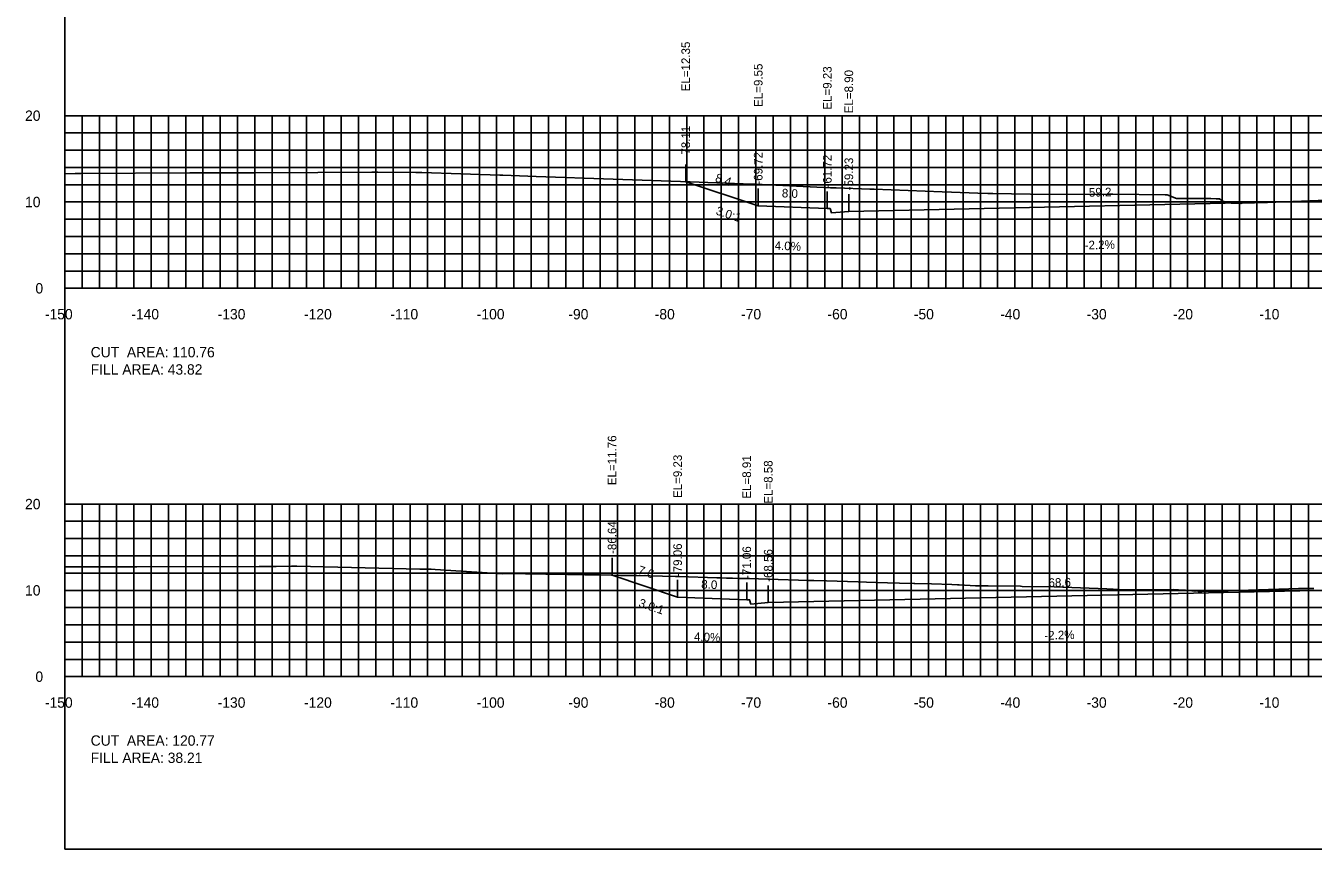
# Model space of a CAD drawing. Extents: x 1797419 to 1809236, y 248759 to 251512.
# Drawn here: x 1804176.5 to 1804325.5, y 250854.9 to 250950.3 of the extents above; entities that cross this region are included whole.
import ezdxf

# ---------------------------------------------------------------- set-up
doc = ezdxf.new("R2010")
doc.units = 0
for name, color, linetype in [('10', 7, 'Continuous'), ('3', 7, 'Continuous'), ('31', 7, 'Continuous'), ('4', 7, 'Continuous'), ('60', 7, 'Continuous'), ('ANNO-TXT', 7, 'Continuous'), ('CL-CNST', 7, 'Continuous'), ('Level 62', 7, 'Continuous'), ('M-ROADS', 7, 'Continuous')]:
    doc.layers.add(name, color=color, linetype=linetype)

msp = doc.modelspace()

# ---------------------------------------------------------------- linework, layer by layer
for p, q in [((1804252.89, 250932.24), (1804252.89, 250934.24)), ((1804261.28, 250929.44), (1804261.28, 250931.44)), ((1804269.28, 250929.12), (1804269.28, 250931.12)), ((1804271.77, 250928.79), (1804271.77, 250930.79)), ((1804244.36, 250886.65), (1804244.36, 250888.65)), ((1804251.95, 250884.12), (1804251.95, 250886.12)), ((1804259.95, 250883.8), (1804259.95, 250885.8)), ((1804262.44, 250883.47), (1804262.44, 250885.47))]:
    msp.add_line(p, q)
msp.add_lwpolyline([(1804181, 250854.89), (1804481, 250854.89), (1804481, 251044.89), (1804181, 251044.89)], close=True)
at = {"layer": '60'}
for p, q in [((1804180.94, 250939.89), (1804181, 250939.89)), ((1804181, 250919.89), (1804181, 250939.89)), ((1804180.94, 250929.89), (1804181, 250929.89)), ((1804180.94, 250919.89), (1804181, 250919.89)), ((1804181, 250919.89), (1804481, 250919.89)), ((1804181, 250919.83), (1804181, 250919.89)), ((1804191, 250919.83), (1804191, 250919.89)), ((1804201, 250919.83), (1804201, 250919.89)), ((1804211, 250919.83), (1804211, 250919.89)), ((1804221, 250919.83), (1804221, 250919.89)), ((1804231, 250919.83), (1804231, 250919.89)), ((1804241, 250919.83), (1804241, 250919.89)), ((1804251, 250919.83), (1804251, 250919.89)), ((1804261, 250919.83), (1804261, 250919.89)), ((1804271, 250919.83), (1804271, 250919.89)), ((1804281, 250919.83), (1804281, 250919.89)), ((1804291, 250919.83), (1804291, 250919.89)), ((1804301, 250919.83), (1804301, 250919.89)), ((1804311, 250919.83), (1804311, 250919.89)), ((1804321, 250919.83), (1804321, 250919.89)), ((1804180.94, 250894.89), (1804181, 250894.89)), ((1804181, 250874.89), (1804181, 250894.89)), ((1804180.94, 250884.89), (1804181, 250884.89)), ((1804180.94, 250874.89), (1804181, 250874.89)), ((1804181, 250874.89), (1804481, 250874.89)), ((1804181, 250874.83), (1804181, 250874.89)), ((1804191, 250874.83), (1804191, 250874.89)), ((1804201, 250874.83), (1804201, 250874.89)), ((1804211, 250874.83), (1804211, 250874.89)), ((1804221, 250874.83), (1804221, 250874.89)), ((1804231, 250874.83), (1804231, 250874.89)), ((1804241, 250874.83), (1804241, 250874.89)), ((1804251, 250874.83), (1804251, 250874.89)), ((1804261, 250874.83), (1804261, 250874.89)), ((1804271, 250874.83), (1804271, 250874.89)), ((1804281, 250874.83), (1804281, 250874.89)), ((1804291, 250874.83), (1804291, 250874.89)), ((1804301, 250874.83), (1804301, 250874.89)), ((1804311, 250874.83), (1804311, 250874.89)), ((1804321, 250874.83), (1804321, 250874.89))]:
    msp.add_line(p, q, dxfattribs=at)
at = {"layer": 'CL-CNST'}
for points in [[(1804252.89, 250932.24), (1804261.28, 250929.44), (1804269.28, 250929.12), (1804269.61, 250929.12), (1804269.77, 250928.62), (1804271.77, 250928.79), (1804331, 250930.09), (1804387.97, 250931.34), (1804389.97, 250931.18), (1804390.14, 250931.68), (1804390.47, 250931.68), (1804392.47, 250931.76), (1804393.5, 250931.78), (1804398.5, 250931.88), (1804399.5, 250931.92), (1804403.32, 250930.65)], [(1804244.36, 250886.65), (1804251.95, 250884.12), (1804259.95, 250883.8), (1804260.28, 250883.8), (1804260.44, 250883.3), (1804262.44, 250883.47), (1804331, 250884.98), (1804380.14, 250886.06), (1804382.14, 250885.89), (1804382.3, 250886.39), (1804382.63, 250886.39), (1804384.63, 250886.47), (1804393.06, 250886.45), (1804398.41, 250886.56), (1804399.41, 250886.6), (1804401.92, 250885.76)]]:
    msp.add_lwpolyline(points, dxfattribs=at)
at = {"layer": 'Level 62'}
for p, q in [((1804181, 250939.89), (1804481, 250939.89)), ((1804181, 250919.89), (1804181, 250939.89)), ((1804183, 250919.89), (1804183, 250939.89)), ((1804185, 250919.89), (1804185, 250939.89)), ((1804187, 250919.89), (1804187, 250939.89)), ((1804189, 250919.89), (1804189, 250939.89)), ((1804191, 250919.89), (1804191, 250939.89)), ((1804193, 250919.89), (1804193, 250939.89)), ((1804195, 250919.89), (1804195, 250939.89)), ((1804197, 250919.89), (1804197, 250939.89)), ((1804199, 250919.89), (1804199, 250939.89)), ((1804201, 250919.89), (1804201, 250939.89)), ((1804203, 250919.89), (1804203, 250939.89)), ((1804205, 250919.89), (1804205, 250939.89)), ((1804207, 250919.89), (1804207, 250939.89)), ((1804209, 250919.89), (1804209, 250939.89)), ((1804211, 250919.89), (1804211, 250939.89)), ((1804213, 250919.89), (1804213, 250939.89)), ((1804215, 250919.89), (1804215, 250939.89)), ((1804217, 250919.89), (1804217, 250939.89)), ((1804219, 250919.89), (1804219, 250939.89)), ((1804221, 250919.89), (1804221, 250939.89)), ((1804223, 250919.89), (1804223, 250939.89)), ((1804225, 250919.89), (1804225, 250939.89)), ((1804227, 250919.89), (1804227, 250939.89)), ((1804229, 250919.89), (1804229, 250939.89)), ((1804231, 250919.89), (1804231, 250939.89)), ((1804233, 250919.89), (1804233, 250939.89)), ((1804235, 250919.89), (1804235, 250939.89)), ((1804237, 250919.89), (1804237, 250939.89)), ((1804239, 250919.89), (1804239, 250939.89)), ((1804241, 250919.89), (1804241, 250939.89)), ((1804243, 250919.89), (1804243, 250939.89)), ((1804245, 250919.89), (1804245, 250939.89)), ((1804247, 250919.89), (1804247, 250939.89)), ((1804249, 250919.89), (1804249, 250939.89)), ((1804251, 250919.89), (1804251, 250939.89)), ((1804253, 250919.89), (1804253, 250939.89)), ((1804255, 250919.89), (1804255, 250939.89)), ((1804257, 250919.89), (1804257, 250939.89)), ((1804259, 250919.89), (1804259, 250939.89)), ((1804261, 250919.89), (1804261, 250939.89)), ((1804263, 250919.89), (1804263, 250939.89)), ((1804265, 250919.89), (1804265, 250939.89)), ((1804267, 250919.89), (1804267, 250939.89)), ((1804269, 250919.89), (1804269, 250939.89)), ((1804271, 250919.89), (1804271, 250939.89)), ((1804273, 250919.89), (1804273, 250939.89)), ((1804275, 250919.89), (1804275, 250939.89)), ((1804277, 250919.89), (1804277, 250939.89)), ((1804279, 250919.89), (1804279, 250939.89)), ((1804281, 250919.89), (1804281, 250939.89)), ((1804283, 250919.89), (1804283, 250939.89)), ((1804285, 250919.89), (1804285, 250939.89)), ((1804287, 250919.89), (1804287, 250939.89)), ((1804289, 250919.89), (1804289, 250939.89)), ((1804291, 250919.89), (1804291, 250939.89)), ((1804293, 250919.89), (1804293, 250939.89)), ((1804295, 250919.89), (1804295, 250939.89)), ((1804297, 250919.89), (1804297, 250939.89)), ((1804299, 250919.89), (1804299, 250939.89)), ((1804301, 250919.89), (1804301, 250939.89)), ((1804303, 250919.89), (1804303, 250939.89)), ((1804305, 250919.89), (1804305, 250939.89)), ((1804307, 250919.89), (1804307, 250939.89)), ((1804309, 250919.89), (1804309, 250939.89)), ((1804311, 250919.89), (1804311, 250939.89)), ((1804313, 250919.89), (1804313, 250939.89)), ((1804315, 250919.89), (1804315, 250939.89)), ((1804317, 250919.89), (1804317, 250939.89)), ((1804319, 250919.89), (1804319, 250939.89)), ((1804321, 250919.89), (1804321, 250939.89)), ((1804323, 250919.89), (1804323, 250939.89)), ((1804325, 250919.89), (1804325, 250939.89)), ((1804181, 250937.89), (1804481, 250937.89)), ((1804181, 250935.89), (1804481, 250935.89)), ((1804181, 250933.89), (1804481, 250933.89)), ((1804181, 250931.89), (1804481, 250931.89)), ((1804181, 250929.89), (1804481, 250929.89)), ((1804181, 250927.89), (1804481, 250927.89)), ((1804181, 250925.89), (1804481, 250925.89)), ((1804181, 250923.89), (1804481, 250923.89)), ((1804181, 250921.89), (1804481, 250921.89)), ((1804181, 250919.89), (1804481, 250919.89)), ((1804181, 250894.89), (1804481, 250894.89)), ((1804181, 250874.89), (1804181, 250894.89)), ((1804183, 250874.89), (1804183, 250894.89)), ((1804185, 250874.89), (1804185, 250894.89)), ((1804187, 250874.89), (1804187, 250894.89)), ((1804189, 250874.89), (1804189, 250894.89)), ((1804191, 250874.89), (1804191, 250894.89)), ((1804193, 250874.89), (1804193, 250894.89)), ((1804195, 250874.89), (1804195, 250894.89)), ((1804197, 250874.89), (1804197, 250894.89)), ((1804199, 250874.89), (1804199, 250894.89)), ((1804201, 250874.89), (1804201, 250894.89)), ((1804203, 250874.89), (1804203, 250894.89)), ((1804205, 250874.89), (1804205, 250894.89)), ((1804207, 250874.89), (1804207, 250894.89)), ((1804209, 250874.89), (1804209, 250894.89)), ((1804211, 250874.89), (1804211, 250894.89)), ((1804213, 250874.89), (1804213, 250894.89)), ((1804215, 250874.89), (1804215, 250894.89)), ((1804217, 250874.89), (1804217, 250894.89)), ((1804219, 250874.89), (1804219, 250894.89)), ((1804221, 250874.89), (1804221, 250894.89)), ((1804223, 250874.89), (1804223, 250894.89)), ((1804225, 250874.89), (1804225, 250894.89)), ((1804227, 250874.89), (1804227, 250894.89)), ((1804229, 250874.89), (1804229, 250894.89)), ((1804231, 250874.89), (1804231, 250894.89)), ((1804233, 250874.89), (1804233, 250894.89)), ((1804235, 250874.89), (1804235, 250894.89)), ((1804237, 250874.89), (1804237, 250894.89)), ((1804239, 250874.89), (1804239, 250894.89)), ((1804241, 250874.89), (1804241, 250894.89)), ((1804243, 250874.89), (1804243, 250894.89)), ((1804245, 250874.89), (1804245, 250894.89)), ((1804247, 250874.89), (1804247, 250894.89)), ((1804249, 250874.89), (1804249, 250894.89)), ((1804251, 250874.89), (1804251, 250894.89)), ((1804253, 250874.89), (1804253, 250894.89)), ((1804255, 250874.89), (1804255, 250894.89)), ((1804257, 250874.89), (1804257, 250894.89)), ((1804259, 250874.89), (1804259, 250894.89)), ((1804261, 250874.89), (1804261, 250894.89)), ((1804263, 250874.89), (1804263, 250894.89)), ((1804265, 250874.89), (1804265, 250894.89)), ((1804267, 250874.89), (1804267, 250894.89)), ((1804269, 250874.89), (1804269, 250894.89)), ((1804271, 250874.89), (1804271, 250894.89)), ((1804273, 250874.89), (1804273, 250894.89)), ((1804275, 250874.89), (1804275, 250894.89)), ((1804277, 250874.89), (1804277, 250894.89)), ((1804279, 250874.89), (1804279, 250894.89)), ((1804281, 250874.89), (1804281, 250894.89)), ((1804283, 250874.89), (1804283, 250894.89)), ((1804285, 250874.89), (1804285, 250894.89)), ((1804287, 250874.89), (1804287, 250894.89)), ((1804289, 250874.89), (1804289, 250894.89)), ((1804291, 250874.89), (1804291, 250894.89)), ((1804293, 250874.89), (1804293, 250894.89)), ((1804295, 250874.89), (1804295, 250894.89)), ((1804297, 250874.89), (1804297, 250894.89)), ((1804299, 250874.89), (1804299, 250894.89)), ((1804301, 250874.89), (1804301, 250894.89)), ((1804303, 250874.89), (1804303, 250894.89)), ((1804305, 250874.89), (1804305, 250894.89)), ((1804307, 250874.89), (1804307, 250894.89)), ((1804309, 250874.89), (1804309, 250894.89)), ((1804311, 250874.89), (1804311, 250894.89)), ((1804313, 250874.89), (1804313, 250894.89)), ((1804315, 250874.89), (1804315, 250894.89)), ((1804317, 250874.89), (1804317, 250894.89)), ((1804319, 250874.89), (1804319, 250894.89)), ((1804321, 250874.89), (1804321, 250894.89)), ((1804323, 250874.89), (1804323, 250894.89)), ((1804325, 250874.89), (1804325, 250894.89)), ((1804181, 250892.89), (1804481, 250892.89)), ((1804181, 250890.89), (1804481, 250890.89)), ((1804181, 250888.89), (1804481, 250888.89)), ((1804181, 250886.89), (1804481, 250886.89)), ((1804181, 250884.89), (1804481, 250884.89)), ((1804181, 250882.89), (1804481, 250882.89)), ((1804181, 250880.89), (1804481, 250880.89)), ((1804181, 250878.89), (1804481, 250878.89)), ((1804181, 250876.89), (1804481, 250876.89)), ((1804181, 250874.89), (1804481, 250874.89))]:
    msp.add_line(p, q, dxfattribs=at)
at = {"layer": 'M-ROADS'}
for points in [[(1804181, 250933.17), (1804182.19, 250933.19), (1804182.66, 250933.19), (1804182.87, 250933.19), (1804195.46, 250933.26), (1804195.7, 250933.26), (1804196.27, 250933.26), (1804202.08, 250933.26), (1804202.64, 250933.26), (1804202.87, 250933.26), (1804210.28, 250933.3), (1804216.56, 250933.33), (1804217.06, 250933.34), (1804217.24, 250933.34), (1804221.64, 250933.3), (1804222.17, 250933.3), (1804222.35, 250933.29), (1804231.36, 250932.99), (1804231.52, 250932.99), (1804231.71, 250932.99), (1804235.56, 250932.85), (1804253.42, 250932.22), (1804260.6, 250931.94), (1804260.76, 250931.94), (1804260.96, 250931.94), (1804269.64, 250931.54), (1804269.8, 250931.53), (1804270.31, 250931.52), (1804274.22, 250931.37), (1804274.35, 250931.37), (1804274.72, 250931.37), (1804282.59, 250931.05), (1804283.64, 250931.02), (1804286.71, 250930.92), (1804287.87, 250930.88), (1804287.94, 250930.88), (1804288.45, 250930.88), (1804294.98, 250930.77), (1804301.73, 250930.8), (1804302.03, 250930.8), (1804302.33, 250930.8), (1804308.39, 250930.72), (1804308.64, 250930.71), (1804309.7, 250930.3), (1804309.71, 250930.3), (1804312.35, 250930.31), (1804312.87, 250930.3), (1804312.9, 250930.3), (1804313, 250930.29), (1804313.11, 250930.29), (1804313.55, 250930.28), (1804313.67, 250930.28), (1804314.31, 250930.26), (1804314.67, 250930.25), (1804315.09, 250929.99), (1804316.05, 250929.74), (1804316.54, 250929.76), (1804316.61, 250929.75), (1804316.7, 250929.75), (1804316.72, 250929.75), (1804316.82, 250929.75), (1804316.99, 250929.74), (1804317.17, 250929.73), (1804317.27, 250929.74), (1804317.29, 250929.74), (1804320.24, 250929.85), (1804330.05, 250930.21)], [(1804181, 250887.6), (1804188.47, 250887.63), (1804188.57, 250887.63), (1804188.62, 250887.63), (1804188.69, 250887.63), (1804188.97, 250887.63), (1804189.28, 250887.63), (1804189.32, 250887.63), (1804189.33, 250887.63), (1804203.49, 250887.64), (1804205.23, 250887.64), (1804205.49, 250887.66), (1804207.25, 250887.68), (1804207.37, 250887.69), (1804207.85, 250887.69), (1804222.09, 250887.36), (1804222.18, 250887.36), (1804222.48, 250887.36), (1804222.82, 250887.36), (1804222.88, 250887.36), (1804222.88, 250887.36), (1804223.4, 250887.34), (1804223.87, 250887.31), (1804231.7, 250886.8), (1804233.01, 250886.86), (1804233.03, 250886.86), (1804233.11, 250886.86), (1804233.21, 250886.85), (1804233.33, 250886.85), (1804233.46, 250886.84), (1804233.62, 250886.84), (1804233.81, 250886.83), (1804234.05, 250886.83), (1804234.33, 250886.82), (1804234.46, 250886.81), (1804235.42, 250886.8), (1804235.48, 250886.8), (1804236.68, 250886.78), (1804239.19, 250886.73), (1804241.19, 250886.7), (1804242.78, 250886.67), (1804243, 250886.67), (1804244.28, 250886.65), (1804245.33, 250886.63), (1804246.21, 250886.62), (1804246.96, 250886.61), (1804247.21, 250886.6), (1804251.72, 250886.5), (1804252.13, 250886.49), (1804256.49, 250886.35), (1804257.02, 250886.34), (1804257.62, 250886.32), (1804258.29, 250886.3), (1804259.06, 250886.28), (1804259.13, 250886.28), (1804259.47, 250886.28), (1804260.29, 250886.26), (1804261.3, 250886.23), (1804262.43, 250886.19), (1804267.09, 250886.04), (1804267.73, 250886.02), (1804269.19, 250885.98), (1804272.84, 250885.87), (1804273.8, 250885.85), (1804274.89, 250885.82), (1804275.04, 250885.81), (1804276.25, 250885.78), (1804277.65, 250885.74), (1804279.3, 250885.69), (1804279.41, 250885.69), (1804281.36, 250885.63), (1804283.71, 250885.56), (1804284.36, 250885.54), (1804284.4, 250885.54), (1804284.54, 250885.53), (1804286.43, 250885.41), (1804287.92, 250885.43), (1804291.63, 250885.36), (1804291.83, 250885.35), (1804295.56, 250885.28), (1804301.66, 250885.05), (1804303.82, 250884.97), (1804305.46, 250884.97), (1804309.4, 250884.98), (1804309.89, 250884.97), (1804309.94, 250884.97), (1804310.74, 250884.91), (1804311.09, 250884.87), (1804311.83, 250884.79), (1804311.88, 250884.79), (1804312.12, 250884.82), (1804312.22, 250884.77), (1804312.25, 250884.74), (1804312.29, 250884.74), (1804312.64, 250884.76), (1804313.76, 250884.81), (1804315.26, 250884.79), (1804315.39, 250884.79), (1804315.41, 250884.79), (1804315.68, 250884.83), (1804322.73, 250885.07), (1804323.84, 250885.11), (1804323.93, 250885.11), (1804324.14, 250885.1), (1804325.62, 250885.1)]]:
    msp.add_lwpolyline(points, dxfattribs=at)

# ---------------------------------------------------------------- texts
for p in [(1804256.3, 250928.47), (1804247.36, 250883.02)]:
    msp.add_text('3.0:1', height=1, rotation=341.5651).set_placement(p)
at = {"layer": '10'}
for s, p in [('-150', (1804178.7, 250916.29)), ('-140', (1804188.7, 250916.29)), ('-130', (1804198.7, 250916.29)), ('-120', (1804208.7, 250916.29)), ('-110', (1804218.7, 250916.29)), ('-100', (1804228.7, 250916.29)), ('-90', (1804239.3, 250916.29)), ('-80', (1804249.3, 250916.29)), ('-70', (1804259.3, 250916.29)), ('-60', (1804269.3, 250916.29)), ('-50', (1804279.3, 250916.29)), ('-40', (1804289.3, 250916.29)), ('-30', (1804299.3, 250916.29)), ('-20', (1804309.3, 250916.29)), ('-10', (1804319.3, 250916.29)), ('-150', (1804178.7, 250871.29)), ('-140', (1804188.7, 250871.29)), ('-130', (1804198.7, 250871.29)), ('-120', (1804208.7, 250871.29)), ('-110', (1804218.7, 250871.29)), ('-100', (1804228.7, 250871.29)), ('-90', (1804239.3, 250871.29)), ('-80', (1804249.3, 250871.29)), ('-70', (1804259.3, 250871.29)), ('-60', (1804269.3, 250871.29)), ('-50', (1804279.3, 250871.29)), ('-40', (1804289.3, 250871.29)), ('-30', (1804299.3, 250871.29)), ('-20', (1804309.3, 250871.29)), ('-10', (1804319.3, 250871.29))]:
    msp.add_text(s, height=1.2, dxfattribs=at).set_placement(p)
at = {"layer": '3'}
for s, p in [('EL=12.35', (1804253.39, 250942.71)), ('EL=9.55', (1804261.78, 250940.91)), ('EL=9.23', (1804269.78, 250940.59)), ('EL=8.90', (1804272.27, 250940.17)), ('-78.11', (1804253.39, 250934.94)), ('-69.72', (1804261.78, 250931.9)), ('-61.72', (1804269.78, 250931.58)), ('-59.23', (1804272.27, 250931.24)), ('EL=11.76', (1804244.86, 250897.08)), ('EL=9.23', (1804252.45, 250895.59)), ('EL=8.91', (1804260.45, 250895.52)), ('EL=8.58', (1804262.94, 250894.93)), ('-86.64', (1804244.86, 250889.11)), ('-79.06', (1804252.45, 250886.53)), ('-71.06', (1804260.45, 250886.21)), ('-68.56', (1804262.94, 250885.88))]:
    msp.add_text(s, height=1, rotation=90, dxfattribs=at).set_placement(p)
at = {"layer": '31'}
for s, p in [('20', (1804176.4, 250939.29)), ('10', (1804176.4, 250929.29)), ('0', (1804177.6, 250919.29)), ('20', (1804176.4, 250894.29)), ('10', (1804176.4, 250884.29)), ('0', (1804177.6, 250874.29))]:
    msp.add_text(s, height=1.2, dxfattribs=at).set_placement(p)
at = {"layer": '4'}
for s, rotation, p in [('8.4', 341.5651, (1804256.22, 250932.29)), ('8.0', 357.7094, (1804264, 250930.43)), ('59.2', 1.2603, (1804299.58, 250930.5)), ('4.0%', 357.7094, (1804263.17, 250924.36)), ('-2.2%', 1.2603, (1804299.09, 250924.39)), ('7.6', 341.5651, (1804247.26, 250886.84)), ('8.0', 357.7094, (1804254.67, 250885.11)), ('68.6', 1.2603, (1804294.9, 250885.28)), ('4.0%', 357.7094, (1804253.83, 250879.04)), ('-2.2%', 1.2603, (1804294.42, 250879.17))]:
    msp.add_text(s, height=1, rotation=rotation, dxfattribs=at).set_placement(p)
at = {"layer": '60'}
for p in [(1804181, 250919.89), (1804181, 250874.89)]:
    msp.add_text('-', height=0.0001, dxfattribs=at).set_placement(p)
at = {"layer": 'ANNO-TXT'}
for s, p in [('CUT  AREA: 110.76', (1804184, 250911.89)), ('FILL AREA: 43.82', (1804184, 250909.89)), ('CUT  AREA: 120.77', (1804184, 250866.89)), ('FILL AREA: 38.21', (1804184, 250864.89))]:
    msp.add_text(s, height=1.2, dxfattribs=at).set_placement(p)

doc.saveas('drawing.dxf')
